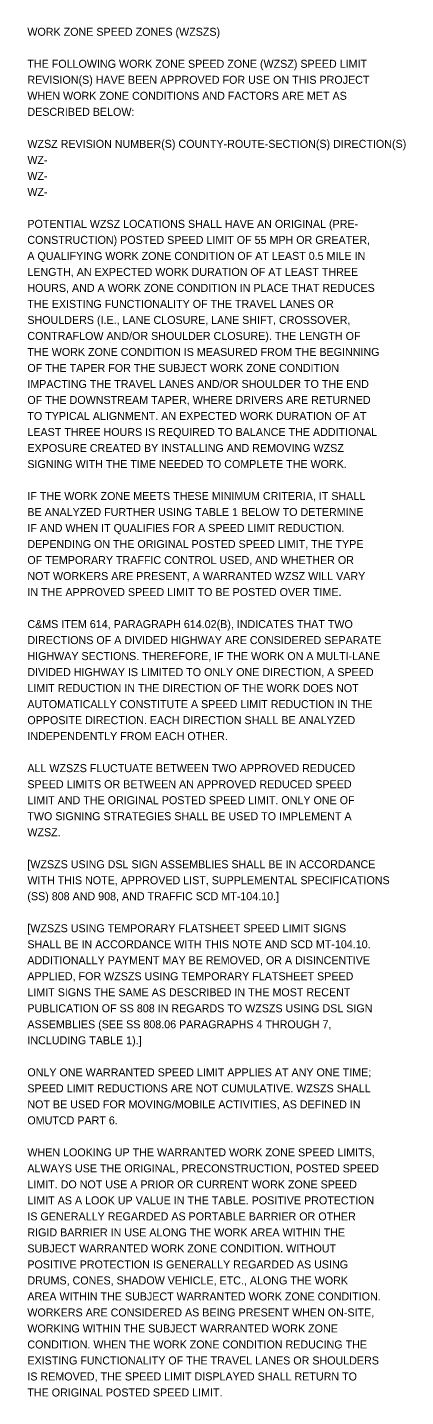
# Model space of a CAD drawing. Extents: x -7.1 to 46.9, y -17.8 to 23.9.
# Drawn here: x 40.28 to 46.9, y -0.08 to 23.87 of the extents above; entities that cross this region are included whole.
import ezdxf

# ---------------------------------------------------------------- set-up
doc = ezdxf.new("R2010")
doc.units = 0
doc.layers.add('SH_Text', color=7, linetype='Continuous')

msp = doc.modelspace()

# ---------------------------------------------------------------- texts
at = {"layer": 'SH_Text'}
for s, p in [('WORK ZONE SPEED ZONES (WZSZS)', (40.284, 23.722)), ('THE FOLLOWING WORK ZONE SPEED ZONE (WZSZ) SPEED LIMIT', (40.284, 23.162)), ('REVISION(S) HAVE BEEN APPROVED FOR USE ON THIS PROJECT', (40.284, 22.882)), ('WHEN WORK ZONE CONDITIONS AND FACTORS ARE MET AS', (40.284, 22.602)), ('DESCRIBED BELOW:', (40.284, 22.322)), ('WZSZ REVISION NUMBER(S) COUNTY-ROUTE-SECTION(S) DIRECTION(S)', (40.284, 21.762)), ('WZ-', (40.284, 21.482)), ('WZ-', (40.284, 21.202)), ('WZ-', (40.284, 20.922)), ('POTENTIAL WZSZ LOCATIONS SHALL HAVE AN ORIGINAL (PRE-', (40.284, 20.362)), ('CONSTRUCTION) POSTED SPEED LIMIT OF 55 MPH OR GREATER,', (40.284, 20.082)), ('A QUALIFYING WORK ZONE CONDITION OF AT LEAST 0.5 MILE IN', (40.284, 19.802)), ('LENGTH, AN EXPECTED WORK DURATION OF AT LEAST THREE', (40.284, 19.522)), ('HOURS, AND A WORK ZONE CONDITION IN PLACE THAT REDUCES', (40.284, 19.242)), ('THE EXISTING FUNCTIONALITY OF THE TRAVEL LANES OR', (40.284, 18.962)), ('SHOULDERS (I.E., LANE CLOSURE, LANE SHIFT, CROSSOVER,', (40.284, 18.682)), ('CONTRAFLOW AND/OR SHOULDER CLOSURE). THE LENGTH OF', (40.284, 18.402)), ('THE WORK ZONE CONDITION IS MEASURED FROM THE BEGINNING', (40.284, 18.122)), ('OF THE TAPER FOR THE SUBJECT WORK ZONE CONDITION', (40.284, 17.842)), ('IMPACTING THE TRAVEL LANES AND/OR SHOULDER TO THE END', (40.284, 17.562)), ('OF THE DOWNSTREAM TAPER, WHERE DRIVERS ARE RETURNED', (40.284, 17.282)), ('TO TYPICAL ALIGNMENT. AN EXPECTED WORK DURATION OF AT', (40.284, 17.002)), ('LEAST THREE HOURS IS REQUIRED TO BALANCE THE ADDITIONAL', (40.284, 16.722)), ('EXPOSURE CREATED BY INSTALLING AND REMOVING WZSZ', (40.284, 16.442)), ('SIGNING WITH THE TIME NEEDED TO COMPLETE THE WORK.', (40.284, 16.162)), ('IF THE WORK ZONE MEETS THESE MINIMUM CRITERIA, IT SHALL', (40.284, 15.602)), ('BE ANALYZED FURTHER USING TABLE 1 BELOW TO DETERMINE', (40.284, 15.322)), ('IF AND WHEN IT QUALIFIES FOR A SPEED LIMIT REDUCTION.', (40.284, 15.042)), ('DEPENDING ON THE ORIGINAL POSTED SPEED LIMIT, THE TYPE', (40.284, 14.762)), ('OF TEMPORARY TRAFFIC CONTROL USED, AND WHETHER OR', (40.284, 14.482)), ('NOT WORKERS ARE PRESENT, A WARRANTED WZSZ WILL VARY', (40.284, 14.202)), ('IN THE APPROVED SPEED LIMIT TO BE POSTED OVER TIME.', (40.284, 13.922)), ('C&MS ITEM 614, PARAGRAPH 614.02(B), INDICATES THAT TWO', (40.284, 13.362)), ('DIRECTIONS OF A DIVIDED HIGHWAY ARE CONSIDERED SEPARATE', (40.284, 13.082)), ('HIGHWAY SECTIONS. THEREFORE, IF THE WORK ON A MULTI-LANE', (40.284, 12.802)), ('DIVIDED HIGHWAY IS LIMITED TO ONLY ONE DIRECTION, A SPEED', (40.284, 12.522)), ('LIMIT REDUCTION IN THE DIRECTION OF THE WORK DOES NOT', (40.284, 12.242)), ('AUTOMATICALLY CONSTITUTE A SPEED LIMIT REDUCTION IN THE', (40.284, 11.962)), ('OPPOSITE DIRECTION. EACH DIRECTION SHALL BE ANALYZED', (40.284, 11.682)), ('INDEPENDENTLY FROM EACH OTHER.', (40.284, 11.402)), ('ALL WZSZS FLUCTUATE BETWEEN TWO APPROVED REDUCED', (40.284, 10.842)), ('SPEED LIMITS OR BETWEEN AN APPROVED REDUCED SPEED', (40.284, 10.562)), ('LIMIT AND THE ORIGINAL POSTED SPEED LIMIT. ONLY ONE OF', (40.284, 10.282)), ('TWO SIGNING STRATEGIES SHALL BE USED TO IMPLEMENT A', (40.284, 10.002)), ('WZSZ.', (40.284, 9.722)), ('[WZSZS USING DSL SIGN ASSEMBLIES SHALL BE IN ACCORDANCE', (40.284, 9.162)), ('WITH THIS NOTE, APPROVED LIST, SUPPLEMENTAL SPECIFICATIONS', (40.284, 8.882)), ('(SS) 808 AND 908, AND TRAFFIC SCD MT-104.10.]', (40.284, 8.602)), ('[WZSZS USING TEMPORARY FLATSHEET SPEED LIMIT SIGNS', (40.284, 8.042)), ('SHALL BE IN ACCORDANCE WITH THIS NOTE AND SCD MT-104.10.', (40.284, 7.762)), ('ADDITIONALLY PAYMENT MAY BE REMOVED, OR A DISINCENTIVE', (40.284, 7.482)), ('APPLIED, FOR WZSZS USING TEMPORARY FLATSHEET SPEED', (40.284, 7.202)), ('LIMIT SIGNS THE SAME AS DESCRIBED IN THE MOST RECENT', (40.284, 6.922)), ('PUBLICATION OF SS 808 IN REGARDS TO WZSZS USING DSL SIGN', (40.284, 6.642)), ('ASSEMBLIES (SEE SS 808.06 PARAGRAPHS 4 THROUGH 7,', (40.284, 6.362)), ('INCLUDING TABLE 1).]', (40.284, 6.082)), ('ONLY ONE WARRANTED SPEED LIMIT APPLIES AT ANY ONE TIME;', (40.284, 5.522)), ('SPEED LIMIT REDUCTIONS ARE NOT CUMULATIVE. WZSZS SHALL', (40.284, 5.242)), ('NOT BE USED FOR MOVING/MOBILE ACTIVITIES, AS DEFINED IN', (40.284, 4.962)), ('OMUTCD PART 6.', (40.284, 4.682)), ('WHEN LOOKING UP THE WARRANTED WORK ZONE SPEED LIMITS,', (40.284, 4.122)), ('ALWAYS USE THE ORIGINAL, PRECONSTRUCTION, POSTED SPEED', (40.284, 3.842)), ('LIMIT. DO NOT USE A PRIOR OR CURRENT WORK ZONE SPEED', (40.284, 3.562)), ('LIMIT AS A LOOK UP VALUE IN THE TABLE. POSITIVE PROTECTION', (40.284, 3.282)), ('IS GENERALLY REGARDED AS PORTABLE BARRIER OR OTHER', (40.284, 3.002)), ('RIGID BARRIER IN USE ALONG THE WORK AREA WITHIN THE', (40.284, 2.722)), ('SUBJECT WARRANTED WORK ZONE CONDITION. WITHOUT', (40.284, 2.442)), ('POSITIVE PROTECTION IS GENERALLY REGARDED AS USING', (40.284, 2.162)), ('DRUMS, CONES, SHADOW VEHICLE, ETC., ALONG THE WORK', (40.284, 1.882)), ('AREA WITHIN THE SUBJECT WARRANTED WORK ZONE CONDITION.', (40.284, 1.602)), ('WORKERS ARE CONSIDERED AS BEING PRESENT WHEN ON-SITE,', (40.284, 1.322)), ('WORKING WITHIN THE SUBJECT WARRANTED WORK ZONE', (40.284, 1.042)), ('CONDITION. WHEN THE WORK ZONE CONDITION REDUCING THE', (40.284, 0.762)), ('EXISTING FUNCTIONALITY OF THE TRAVEL LANES OR SHOULDERS', (40.284, 0.482)), ('IS REMOVED, THE SPEED LIMIT DISPLAYED SHALL RETURN TO', (40.284, 0.202)), ('THE ORIGINAL POSTED SPEED LIMIT.', (40.284, -0.078))]:
    msp.add_text(s, height=0.14, dxfattribs=at).set_placement(p)

doc.saveas('drawing.dxf')
